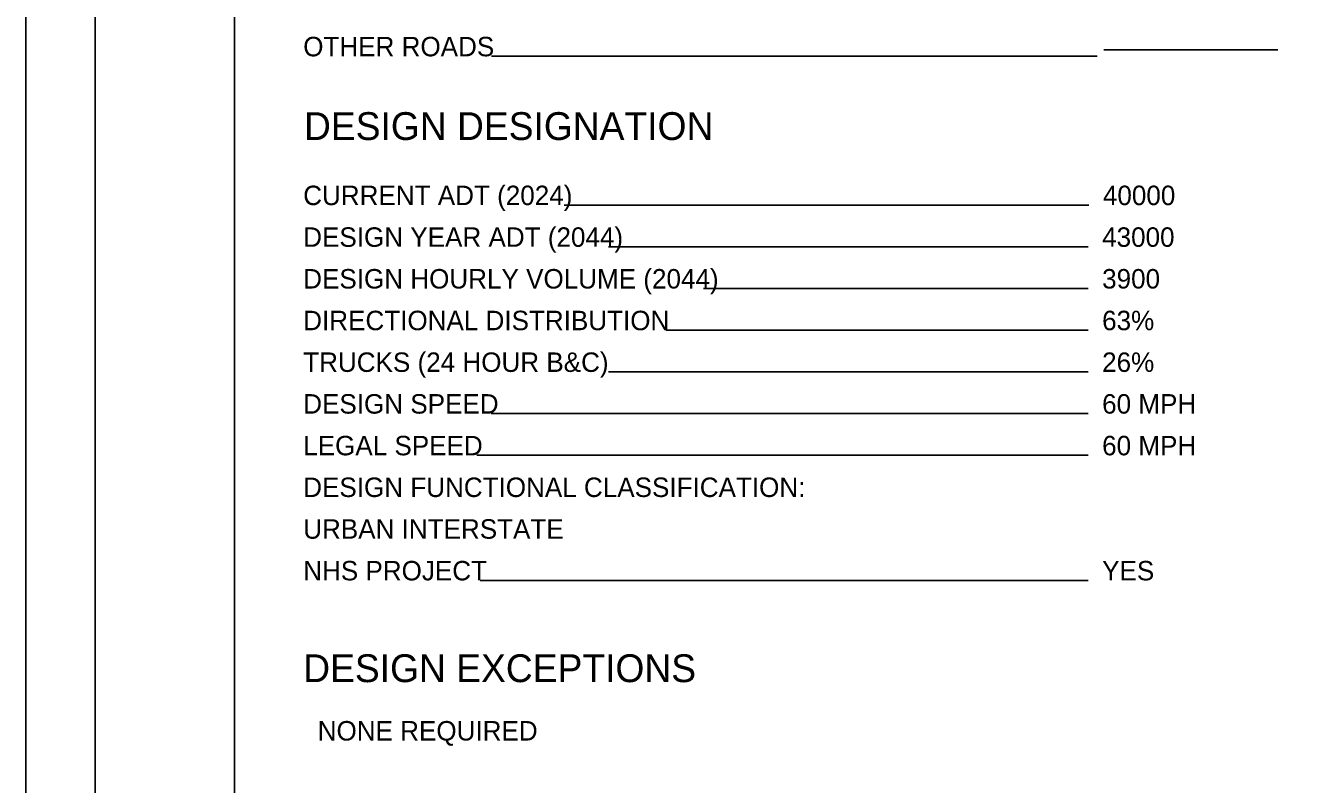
# Model space of a CAD drawing. Extents: x 0 to 40.2, y 0 to 22.
# Drawn here: x 0 to 9.25, y 5.64 to 11.1 of the extents above; entities that cross this region are included whole.
import ezdxf

# ---------------------------------------------------------------- set-up
doc = ezdxf.new("R2010")
doc.units = 0
for name, color, linetype in [('GM_X_Adjacent_County', 7, 'Continuous'), ('GM_X_Adjacent_County_Text', 7, 'Continuous'), ('GM_X_County', 7, 'Continuous'), ('GM_X_Township', 7, 'Continuous')]:
    doc.layers.add(name, color=color, linetype=linetype)

msp = doc.modelspace()

# ---------------------------------------------------------------- linework, layer by layer
at = {"layer": 'GM_X_Adjacent_County'}
for p, q in [((9, 10.9223), (7.75, 10.9223)), ((7.7, 10.8767), (3.3471, 10.8767)), ((7.6424, 9.8062), (3.871, 9.8062)), ((7.6368, 9.5062), (4.1885, 9.5062)), ((7.6368, 9.2062), (4.8723, 9.2062)), ((7.6368, 8.9062), (4.6037, 8.9062)), ((7.6368, 8.6062), (4.1885, 8.6062)), ((7.6368, 8.3062), (3.346, 8.3062)), ((7.6368, 8.0062), (3.2422, 8.0062)), ((7.6368, 7.1062), (3.2669, 7.1062))]:
    msp.add_line(p, q, dxfattribs=at)
at = {"layer": 'GM_X_County'}
msp.add_lwpolyline([(0, 0), (34, 0), (34, 22), (0, 22)], close=True, dxfattribs=at)
at = {"layer": 'GM_X_Township'}
for points in [[(0.5, 21.5), (1.5, 21.5), (1.5, 0.5), (0.5, 0.5)], [(1.5, 21.5), (33.5, 21.5), (33.5, 0.5), (1.5, 0.5)]]:
    msp.add_lwpolyline(points, close=True, dxfattribs=at)

# ---------------------------------------------------------------- texts
at = {"layer": 'GM_X_Adjacent_County'}
msp.add_text('DESIGN DESIGNATION', height=0.2, dxfattribs=at).set_placement((2, 10.2747))
at = {"layer": 'GM_X_Adjacent_County_Text'}
for s, height, p in [('OTHER ROADS', 0.14, (1.9944, 10.8767)), ('CURRENT ADT (2024)', 0.14, (1.9944, 9.8062)), ('40000 ', 0.14, (7.7424, 9.8062)), ('DESIGN YEAR ADT (2044)', 0.14, (1.9944, 9.5062)), ('43000 ', 0.14, (7.7368, 9.5062)), ('DESIGN HOURLY VOLUME (2044)', 0.14, (1.9944, 9.2062)), ('3900  ', 0.14, (7.7368, 9.2062)), ('DIRECTIONAL DISTRIBUTION', 0.14, (1.9944, 8.9062)), ('63%   ', 0.14, (7.7368, 8.9062)), ('TRUCKS (24 HOUR B&C)', 0.14, (1.9944, 8.6062)), ('26%   ', 0.14, (7.7368, 8.6062)), ('DESIGN SPEED', 0.14, (1.9944, 8.3062)), ('60 MPH', 0.14, (7.7368, 8.3062)), ('LEGAL SPEED', 0.14, (1.9944, 8.0062)), ('60 MPH', 0.14, (7.7368, 8.0062)), ('DESIGN FUNCTIONAL CLASSIFICATION:', 0.14, (1.9944, 7.7062)), ('URBAN INTERSTATE                                ', 0.14, (1.9944, 7.4062)), ('NHS PROJECT', 0.14, (1.9944, 7.1062)), ('YES   ', 0.14, (7.7368, 7.1062)), ('DESIGN EXCEPTIONS', 0.2, (1.9944, 6.3744)), ('  NONE REQUIRED                          ', 0.14, (1.9944, 5.9544))]:
    msp.add_text(s, height=height, dxfattribs=at).set_placement(p)

doc.saveas('drawing.dxf')
